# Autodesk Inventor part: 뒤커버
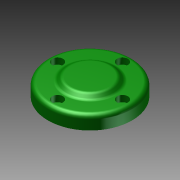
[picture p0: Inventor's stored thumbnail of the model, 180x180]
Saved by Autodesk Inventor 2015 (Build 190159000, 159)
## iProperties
Created: 2025-08
Part Number: 뒤커버
Material: 일반
Document SubType Name: Modeling
Designer: USER
Density: 1 g/cm^3
Appearance: 기본값
Author: USER
Author: jhkim
Creation Date: 2025-08-05
Sending System: Autodesk Inventor 2026
Preprocessor: ST-DEVELOPER v20.1
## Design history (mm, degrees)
node "뒤커버1"
node "솔리드1"
node "기준1"
